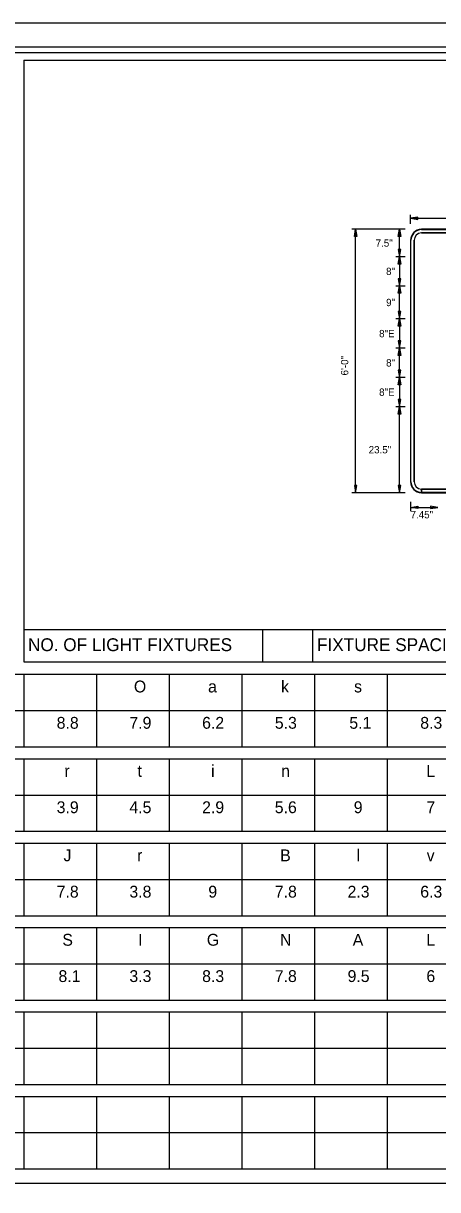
# Model space of a CAD drawing. Extents: x 1274.1 to 1363.1, y 833.5 to 890.6.
# Drawn here: x 1290.18 to 1299.62, y 864.07 to 890.63 of the extents above; entities that cross this region are included whole.
import ezdxf

# ---------------------------------------------------------------- set-up
doc = ezdxf.new("R2010")
doc.units = 0
for name, color, linetype in [('GSBWFill', 7, 'Continuous'), ('GSColorFill', 7, 'Continuous'), ('GSDims', 7, 'Continuous'), ('GSOutline', 7, 'Continuous'), ('GSSign', 7, 'Continuous'), ('PlotBorder_dp', 7, 'Continuous'), ('SheetBorder_dp', 7, 'Continuous'), ('SheetLinesMisc2_dp', 7, 'Continuous'), ('TextMinor', 7, 'Continuous')]:
    doc.layers.add(name, color=color, linetype=linetype)

msp = doc.modelspace()

# ---------------------------------------------------------------- linework, layer by layer
at = {"layer": 'GSBWFill'}
for p, q in [((1309.75, 885.942), (1299.25, 885.942)), ((1299.25, 885.859), (1309.75, 885.859)), ((1299, 885.692), (1299, 880.192)), ((1299.083, 880.192), (1299.083, 885.692)), ((1299.25, 879.942), (1299.25, 880.025)), ((1309.75, 880.025), (1299.25, 880.025)), ((1299.25, 880.025), (1299.25, 879.942)), ((1299.25, 879.942), (1309.75, 879.942))]:
    msp.add_line(p, q, dxfattribs=at)
for centre, radius, start, end in [((1299.25, 885.692), 0.25, 90, 180), ((1299.25, 885.692), 0.167, 90, 180), ((1299.25, 880.192), 0.25, 180, 270), ((1299.25, 880.192), 0.167, 180, 270)]:
    msp.add_arc(centre, radius, start, end, dxfattribs=at)
at = {"layer": 'GSColorFill'}
for p, q in [((1309.75, 885.942), (1299.25, 885.942)), ((1309.75, 885.942), (1299.25, 885.942)), ((1309.75, 885.942), (1299.25, 885.942)), ((1299.25, 885.934), (1309.75, 885.934)), ((1299.25, 885.859), (1309.75, 885.859)), ((1299, 885.692), (1299, 880.192)), ((1299, 885.692), (1299, 880.192)), ((1299, 885.692), (1299, 880.192)), ((1299.008, 880.192), (1299.008, 885.692)), ((1299.083, 880.192), (1299.083, 885.692)), ((1299.25, 879.942), (1299.25, 880.025)), ((1309.75, 880.025), (1299.25, 880.025)), ((1299.25, 880.025), (1299.25, 879.942)), ((1299.25, 879.942), (1299.25, 879.95)), ((1309.75, 879.95), (1299.25, 879.95)), ((1299.25, 879.95), (1299.25, 879.942)), ((1299.25, 879.942), (1309.75, 879.942)), ((1299.25, 879.942), (1309.75, 879.942)), ((1299.25, 879.942), (1309.75, 879.942))]:
    msp.add_line(p, q, dxfattribs=at)
for centre, radius, start, end in [((1299.25, 885.692), 0.25, 90, 180), ((1299.25, 885.692), 0.25, 90, 180), ((1299.25, 885.692), 0.25, 90, 180), ((1299.25, 885.692), 0.242, 90, 180), ((1299.25, 885.692), 0.167, 90, 180), ((1299.25, 880.192), 0.25, 180, 270), ((1299.25, 880.192), 0.25, 180, 270), ((1299.25, 880.192), 0.25, 180, 270), ((1299.25, 880.192), 0.242, 180, 270), ((1299.25, 880.192), 0.167, 180, 270)]:
    msp.add_arc(centre, radius, start, end, dxfattribs=at)
at = {"layer": 'GSDims'}
for p, q in [((1299, 886.067), (1299, 886.275)), ((1299, 886.192), (1310, 886.192)), ((1299, 886.067), (1299, 886.067)), ((1297.875, 885.942), (1297.666, 885.942)), ((1297.75, 879.942), (1297.75, 885.942)), ((1298.875, 885.942), (1297.875, 885.942)), ((1298.875, 885.942), (1298.666, 885.942)), ((1298.75, 885.317), (1298.75, 885.942)), ((1298.875, 885.317), (1298.666, 885.317)), ((1298.875, 885.317), (1298.666, 885.317)), ((1298.75, 885.317), (1298.75, 884.65)), ((1298.875, 884.65), (1298.666, 884.65)), ((1298.875, 884.65), (1298.666, 884.65)), ((1298.75, 883.9), (1298.75, 884.65)), ((1298.875, 883.9), (1298.666, 883.9)), ((1298.875, 883.9), (1298.666, 883.9)), ((1298.75, 883.9), (1298.75, 883.234)), ((1298.875, 883.234), (1298.666, 883.234)), ((1298.875, 883.234), (1298.666, 883.234)), ((1298.75, 882.567), (1298.75, 883.234)), ((1298.875, 882.567), (1298.666, 882.567)), ((1298.875, 882.567), (1298.666, 882.567)), ((1298.75, 882.567), (1298.75, 881.9)), ((1298.875, 881.9), (1298.666, 881.9)), ((1298.875, 881.9), (1298.666, 881.9)), ((1298.75, 879.942), (1298.75, 881.9)), ((1297.875, 879.942), (1297.666, 879.942)), ((1298.875, 879.942), (1297.875, 879.942)), ((1298.875, 879.942), (1298.666, 879.942)), ((1299, 879.734), (1299, 879.525)), ((1299, 879.734), (1299, 879.525)), ((1299, 879.609), (1299.622, 879.609))]:
    msp.add_line(p, q, dxfattribs=at)
for points in [[(1299, 886.192), (1299.166, 886.164), (1299.166, 886.22)], [(1297.75, 885.942), (1297.777, 885.775), (1297.722, 885.775)], [(1298.75, 885.942), (1298.777, 885.775), (1298.722, 885.775)], [(1298.75, 885.317), (1298.777, 885.484), (1298.722, 885.484)], [(1298.75, 885.317), (1298.777, 885.15), (1298.722, 885.15)], [(1298.75, 884.65), (1298.777, 884.817), (1298.722, 884.817)], [(1298.75, 884.65), (1298.777, 884.484), (1298.722, 884.484)], [(1298.75, 883.9), (1298.777, 884.067), (1298.722, 884.067)], [(1298.75, 883.9), (1298.777, 883.734), (1298.722, 883.734)], [(1298.75, 883.234), (1298.777, 883.4), (1298.722, 883.4)], [(1298.75, 883.234), (1298.777, 883.067), (1298.722, 883.067)], [(1298.75, 882.567), (1298.777, 882.734), (1298.722, 882.734)], [(1298.75, 882.567), (1298.777, 882.4), (1298.722, 882.4)], [(1298.75, 881.9), (1298.777, 882.067), (1298.722, 882.067)], [(1298.75, 881.9), (1298.777, 881.734), (1298.722, 881.734)], [(1297.75, 879.942), (1297.777, 880.109), (1297.722, 880.109)], [(1298.75, 879.942), (1298.777, 880.109), (1298.722, 880.109)], [(1299, 879.609), (1299.166, 879.636), (1299.166, 879.581)], [(1299.622, 879.609), (1299.455, 879.636), (1299.455, 879.581)]]:
    msp.add_lwpolyline(points, close=True, dxfattribs=at)
at = {"layer": 'GSOutline'}
for p, q in [((1309.75, 885.942), (1299.25, 885.942)), ((1309.75, 885.859), (1299.25, 885.859)), ((1299, 885.692), (1299, 880.192)), ((1299.083, 885.692), (1299.083, 880.192)), ((1299.25, 880.025), (1309.75, 880.025)), ((1299.25, 879.942), (1309.75, 879.942))]:
    msp.add_line(p, q, dxfattribs=at)
for centre, radius, start, end in [((1299.25, 885.692), 0.25, 90, 180), ((1299.25, 885.692), 0.167, 90, 180), ((1299.25, 880.192), 0.25, 180, 270), ((1299.25, 880.192), 0.167, 180, 270)]:
    msp.add_arc(centre, radius, start, end, dxfattribs=at)
at = {"layer": 'PlotBorder_dp'}
msp.add_lwpolyline([(1274.135, 833.481), (1363.097, 833.481), (1363.097, 890.634), (1274.135, 890.634)], close=True, dxfattribs=at)
at = {"layer": 'SheetBorder_dp'}
msp.add_line((1277.101, 890.095), (1360.132, 890.095), dxfattribs=at)
at = {"layer": 'SheetLinesMisc2_dp'}
for p, q in [((1277.247, 889.967), (1359.988, 889.967)), ((1290.196, 889.796), (1318.336, 889.796)), ((1290.196, 889.796), (1290.196, 876.088)), ((1290.196, 876.823), (1318.336, 876.823)), ((1295.631, 876.823), (1295.631, 876.088)), ((1296.77, 876.823), (1296.77, 876.088)), ((1290.196, 876.088), (1318.336, 876.088)), ((1277.644, 875.806), (1318.336, 875.806)), ((1290.196, 875.806), (1290.196, 874.153)), ((1291.851, 875.806), (1291.851, 874.153)), ((1293.506, 875.806), (1293.506, 874.153)), ((1295.161, 875.806), (1295.161, 874.153)), ((1296.817, 875.806), (1296.817, 874.153)), ((1298.472, 875.806), (1298.472, 874.153)), ((1277.644, 874.979), (1318.336, 874.979)), ((1277.644, 874.153), (1318.336, 874.153)), ((1277.644, 873.883), (1318.336, 873.883)), ((1290.196, 873.883), (1290.196, 872.23)), ((1291.851, 873.883), (1291.851, 872.23)), ((1293.506, 873.883), (1293.506, 872.23)), ((1295.161, 873.883), (1295.161, 872.23)), ((1296.817, 873.883), (1296.817, 872.23)), ((1298.472, 873.883), (1298.472, 872.23)), ((1277.644, 873.056), (1318.336, 873.057)), ((1277.644, 872.23), (1318.336, 872.23)), ((1277.644, 871.96), (1318.336, 871.96)), ((1290.196, 871.96), (1290.196, 870.307)), ((1291.851, 871.96), (1291.851, 870.307)), ((1293.506, 871.96), (1293.506, 870.307)), ((1295.161, 871.96), (1295.161, 870.307)), ((1296.817, 871.96), (1296.817, 870.307)), ((1298.472, 871.96), (1298.472, 870.307)), ((1277.644, 871.134), (1318.336, 871.134)), ((1277.644, 870.307), (1318.336, 870.307)), ((1277.644, 870.038), (1318.336, 870.038)), ((1290.196, 870.038), (1290.196, 868.384)), ((1291.851, 870.038), (1291.851, 868.384)), ((1293.506, 870.038), (1293.506, 868.384)), ((1295.161, 870.038), (1295.161, 868.384)), ((1296.817, 870.038), (1296.817, 868.384)), ((1298.472, 870.038), (1298.472, 868.384)), ((1277.644, 869.211), (1318.336, 869.211)), ((1277.644, 868.384), (1318.336, 868.384)), ((1277.644, 868.115), (1318.336, 868.115)), ((1290.196, 868.115), (1290.196, 866.462)), ((1291.851, 868.115), (1291.851, 866.462)), ((1293.506, 868.115), (1293.506, 866.462)), ((1295.161, 868.115), (1295.161, 866.462)), ((1296.817, 868.115), (1296.817, 866.462)), ((1298.472, 868.115), (1298.472, 866.462)), ((1277.644, 867.288), (1318.336, 867.288)), ((1277.644, 866.462), (1318.336, 866.462)), ((1277.644, 866.192), (1318.336, 866.192)), ((1290.196, 866.192), (1290.196, 864.539)), ((1291.851, 866.192), (1291.851, 864.539)), ((1293.506, 866.192), (1293.506, 864.539)), ((1295.161, 866.192), (1295.161, 864.539)), ((1296.817, 866.192), (1296.817, 864.539)), ((1298.472, 866.192), (1298.472, 864.539)), ((1277.644, 865.366), (1318.336, 865.366)), ((1277.644, 864.539), (1318.336, 864.539)), ((1277.247, 864.214), (1359.988, 864.214))]:
    msp.add_line(p, q, dxfattribs=at)

# ---------------------------------------------------------------- texts
at = {"layer": 'GSDims'}
for s, p in [('7.5"', (1298.206, 885.546)), ('8"', (1298.444, 884.9)), ('9"', (1298.444, 884.192)), ('8"E', (1298.285, 883.484)), ('8"', (1298.444, 882.817)), ('8"E', (1298.285, 882.15)), ('23.5"', (1298.047, 880.838)), ('7.45"', (1299.001, 879.359))]:
    msp.add_text(s, height=0.1667, dxfattribs=at).set_placement(p)
msp.add_text('6\'-0"', height=0.1667, rotation=90, dxfattribs=at).set_placement((1297.583, 882.613))
at = {"layer": 'GSSign'}
for s, height, p in [('O', 0.27, (1292.701, 875.393)), ('k', 0.27, (1296.052, 875.393)), ('a', 0.27, (1294.39, 875.393)), ('s', 0.27, (1297.715, 875.393)), ('8.8', 0.2696, (1290.943, 874.566)), ('7.9', 0.2696, (1292.599, 874.566)), ('6.2', 0.2696, (1294.255, 874.566)), ('5.3', 0.2696, (1295.911, 874.566)), ('5.1', 0.2696, (1297.607, 874.566)), ('8.3', 0.2696, (1299.222, 874.566)), ('r', 0.27, (1291.119, 873.47)), ('t', 0.27, (1292.784, 873.47)), ('i', 0.27, (1294.459, 873.47)), ('n', 0.27, (1296.054, 873.47)), ('L', 0.27, (1299.358, 873.47)), ('3.9', 0.2696, (1290.943, 872.643)), ('4.5', 0.2696, (1292.599, 872.643)), ('2.9', 0.2696, (1294.255, 872.643)), ('5.6', 0.2696, (1295.909, 872.643)), ('9', 0.27, (1297.707, 872.643)), ('7', 0.27, (1299.362, 872.643)), ('J', 0.27, (1291.099, 871.547)), ('r', 0.27, (1292.775, 871.547)), ('B', 0.27, (1296.032, 871.547)), ('l', 0.27, (1297.77, 871.547)), ('v', 0.27, (1299.368, 871.547)), ('7.8', 0.2696, (1290.943, 870.72)), ('3.8', 0.2696, (1292.599, 870.72)), ('9', 0.27, (1294.396, 870.72)), ('7.8', 0.2696, (1295.91, 870.72)), ('2.3', 0.2696, (1297.566, 870.72)), ('6.3', 0.2696, (1299.222, 870.72)), ('S', 0.27, (1291.072, 869.624)), ('I', 0.27, (1292.799, 869.624)), ('G', 0.27, (1294.362, 869.624)), ('N', 0.27, (1296.028, 869.624)), ('A', 0.27, (1297.684, 869.624)), ('L', 0.27, (1299.358, 869.624)), ('8.1', 0.2696, (1290.984, 868.797)), ('3.3', 0.2696, (1292.599, 868.797)), ('8.3', 0.2696, (1294.255, 868.797)), ('7.8', 0.2696, (1295.91, 868.797)), ('9.5', 0.2696, (1297.567, 868.797)), ('6', 0.27, (1299.362, 868.797))]:
    msp.add_text(s, height=height, dxfattribs=at).set_placement(p)
at = {"layer": 'TextMinor'}
for s, p in [('NO. OF LIGHT FIXTURES', (1290.29, 876.334)), ('FIXTURE SPACING', (1296.871, 876.334))]:
    msp.add_text(s, height=0.2923, dxfattribs=at).set_placement(p)

doc.saveas('drawing.dxf')
